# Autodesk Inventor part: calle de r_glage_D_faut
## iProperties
Created: 2011-10
Part Number: calle de r_glage_D_faut
Document SubType Name: Modeling
Designer: Bruno
Author: Bruno
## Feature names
1. Base1
